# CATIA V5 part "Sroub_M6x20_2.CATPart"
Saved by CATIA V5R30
Part number: Sroub_M6x20_2
Nomenclature: E1220/6/20
Description: MEUSBURGER
Publications: "DrillHole", "TapHole", "Base"
Bounding box of the stored display mesh (mm): x -5.992 to 5.992, y -5.992 to 5.992, z -3.3 to 16.7
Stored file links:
  E:\Bakalarka\Model\Forma_v7\Sroub_M6x20_2.CATPart
  E:\dev\MoldDesign\intel_a\startup\components\MoldCatalog\CountersunkScrew\Meusburger\CountersunkScrew_E1220\TableE1220.txt
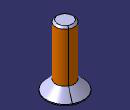
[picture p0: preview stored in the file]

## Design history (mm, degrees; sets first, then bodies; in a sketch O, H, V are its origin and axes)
Parameters
  Ref = "E1220/6/20" {design table}
  D = 6 mm {design table}
  D1 = 6 mm {design table}
  D3 = 12 mm {design table}
  L = 20 mm {design table}
  L3 = 3.3 mm {design table}
  SW = 4 mm {design table}
  L1 = 0.3 mm {design table}
  L4 = 2.5 mm {design table}
  d2kern = 4.77 mm {design table}
  F = 0.615 mm {design table}
  W = 90 deg {design table}
  kd1 = 6.6 mm {design table}
  kl1 = 14 mm {design table}
  kl = 25 mm {design table}
  dkern = 4.92 mm {design table}
  C = 5 mm {design table}
  ThreadString = "M6" {design table}
  Mat = "" {design table}
  HeatTreat = "" {design table}
  SupplierRef = "Meusburger 2017"
  BmpRef = "F_MldCountersunkScrew_D_L"
  DrillHole_Length = 225 mm
  HeadThick = 3.3 mm {= L3}
  HeadDiam = 12 mm {= D3}
  ScrewThread = 16.7 mm {= Thread1.Depth}
  ScrewPitch = 1 mm {= Thread1.Pitch}
Set1 "BaseBody"
  Point1 "Base": (0, 0, 0)
  Plane1: type Offset, RefPlane face of Shaft1 from Sketch1.L1, Offset 225 {= DrillHole_Length}, reversed
Body1 "PartBody" (main body)
  Sketch1 on yz-plane, origin (0, 0, 0), H (0, 0, -1), V (0, 1, 0)
    point P1 (3.3, 0)
    line L1 (3.3, 0) -> (3.3, -6)
    point P2 (3.3, -6)
    point P3 (-16.7, -3)
    point P4 (-16.7, -3)
    line L2 (-16.7, -3) -> (-16.7, 0)
    point P5 (-16.7, 0)
    point P6 (-16.7, 0)
    axis line L3 (-16.7, 0) -> (3.3, 0)
    point P7 (3.3, 0)
    point P8 (0, -3)
    line L4 (0, -3) -> (-16.7, -3)
    point P9 (0, -3)
    line L5 (0, -3) -> (3, -6)
    line L6 (3, -6) -> (3.3, -6)
    distance L1 L2 = 20 {= L}
    distance L4 L3 = 3 {= D /2}
    length L1 = 6 {= D3 /2}
    distance P9 P2 H = 3.3 {= L3}
    angle L5 L6 = 45 {= W/2}
    coincidence: P5 L3, P1 L3, L3 H, P4 P3, P9 P8, P6 L2, P7 L1, V P8
    vertical: L1 V, L2 V
    horizontal: L4 H, L6 H
  Shaft1: profile Sketch1, axis Sketch1.L3, angle 360
  Sketch2 on face of Shaft1 from Sketch1.L1, origin (0, 0, -3.3), H (1, 0, 0), V (0, -1, 0)
    point P1 (1.1547, 2)
    point P2 (-1.1547, 2)
    point P3 (-2.3094, 0)
    point P4 (-1.1547, -2)
    point P5 (1.1547, -2)
    point P6 (2.3094, 0)
    point P7 (0, 2)
    line L1 (1.1547, 2) -> (-1.1547, 2)
    line L2 (-1.1547, 2) -> (-2.3094, 0)
    line L3 (-2.3094, 0) -> (-1.1547, -2)
    line L4 (-1.1547, -2) -> (1.1547, -2)
    line L5 (1.1547, -2) -> (2.3094, 0)
    line L6 (2.3094, 0) -> (1.1547, 2)
    construction line L7 (0, 0) -> (0, 2)
    construction circle A1 centre (0, 0) radius 2.3094
    construction arc A2 centre (1.1547, -2) radius 2.3094 from (-1.1547, -2) to (2.3094, 0) cw
    construction arc A3 centre (-1.1547, 2) radius 2.3094 from (-2.3094, 0) to (1.1547, 2) ccw
    point P8 (1.1547, -2)
    point P9 (-1.1547, 2)
    distance L1 L4 = 4 {= SW}
    vertical: L7 V
    coincidence: A1 P1, A1 P2, A1 P3, A1 P4, A1 P5, A1 P6, A2 P4, A2 P6, A2 O, P8 P5, A3 P3, A3 P1, A3 O, P9 P2
    midpoint: P7 L1
  Pocket1: profile Sketch2, direction (0, 0, 1), length 1.65 {= L3 /2}
  Thread1: "M6", diameter 6, depth 16.7 {= L-L3}, pitch 1, on face of Shaft1 from Sketch1.L4, from face of Shaft1 from Sketch1.L2
  Chamfer1: length 0.615 {= F}, angle 45, on edge [face of Shaft1 from Sketch1.L2 | face of Shaft1 from Sketch1.L4]
Body2 "DrillHole"
  Sketch3 on Plane1, origin (0, 0, -228.3), H (1, 0, 0), V (0, 1, 0)
    point P1 (0, 0)
    reference projected circle E1 centre (0, 0) radius 6 from edge [face of Shaft1 from Sketch1.L5 | face of Shaft1 from Sketch1.L6]
    concentricity: P1 E1
  Hole1: placed by Sketch3, at (0, 0, -228.3) direction (0, 0, 1), diameter 6.6 {= kd1}, depth 245 {= DrillHole_Length +L}, type CounterDrilledType, Diameter 6.6 {= kd1}, DiameterThread 11, Pas 1, Profile a sketch, Sketch Sketch3, ThreadDepth 10, Angle 90, Depth 225.3 {= DrillHole_Length +L1}, Diameter 12 {= D3}
Body3 "TapHole"
  Sketch4 on Plane1, origin (0, 0, -228.3), H (1, 0, 0), V (0, 1, 0)
    point P1 (0, 0)
    reference projected circle E1 centre (0, 0) radius 6 from edge [face of Shaft1 from Sketch1.L5 | face of Shaft1 from Sketch1.L6]
    concentricity: E1 P1
  Hole2: placed by Sketch4, at (0, 0, -228.3) direction (0, 0, 1), diameter 4.917, depth 250 {= DrillHole_Length +kl}, V-bottom angle 90, threaded "M6", thread diameter 6, thread depth 250 {= DrillHole_Length +kl}, pitch 1
Relations
  design table "TableE1220", configuration 34, drives Ref, D, D1, D3, L, L3, SW, L1, L4, d2kern, F, W, kd1, kl1, kl, dkern, C, ThreadString, Mat, HeatTreat
  Thread1.ThreadDescription = ThreadString
  Hole2.ThreadDescription = ThreadString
